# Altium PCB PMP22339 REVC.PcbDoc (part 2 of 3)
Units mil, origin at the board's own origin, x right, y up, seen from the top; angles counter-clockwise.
Board outline 4555 x 3750 mil, 4 copper layers (Top Layer, Signal Layer 2, Signal Layer 3, Bottom Layer), stack 62.6 mil thick; 180 components, 83 nets, 384 pads, 132 vias.
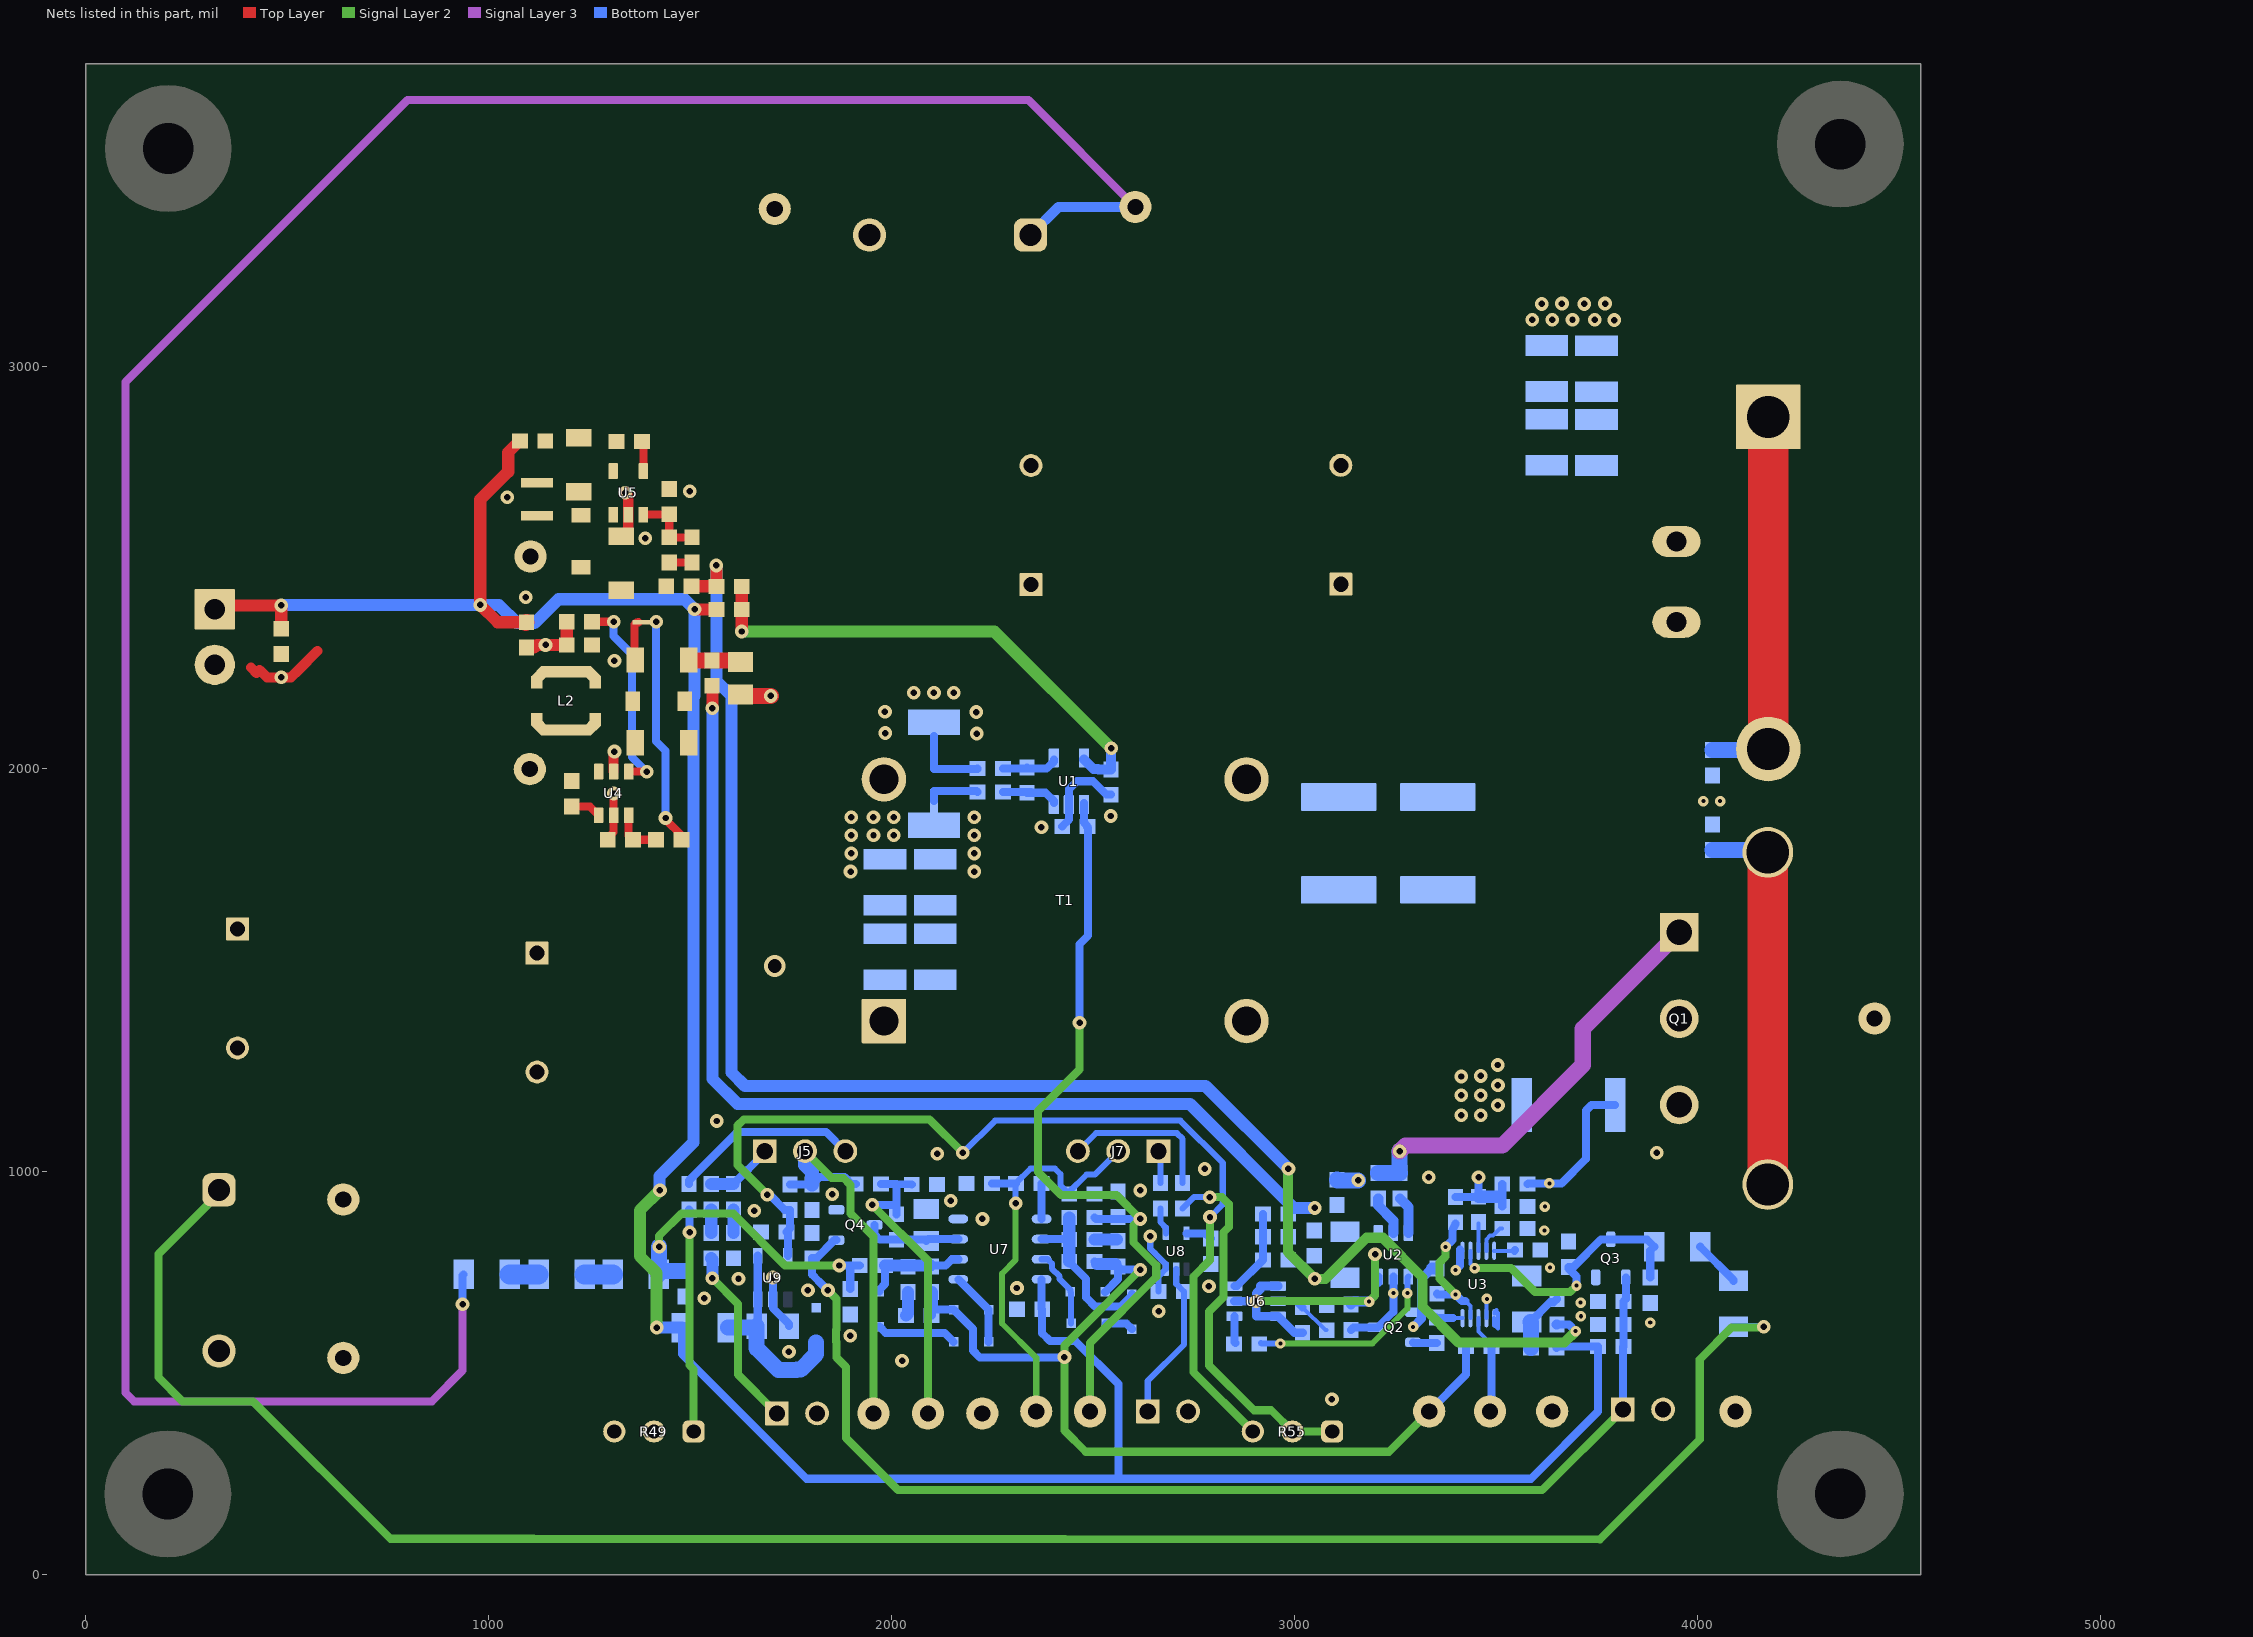
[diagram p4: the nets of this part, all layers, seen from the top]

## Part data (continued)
L2: library part CMP-0061351-2, "Inductor, Shielded Drum Core, Ferrite, 33 uH, 0.68 A, 0.42 ohm, SMD", Manufacturer=Coilcraft, Value1="0.42 ohm", Value2=0.68A, ValueDisplayed=33uH
LOGO2 LOGO3: library part CMP-0074835-1, "IEC 61010-1 High Voltage Warning"
Logo2: library part CMP-0074847-1, "FCC_disclaimer"
Logo3: library part CMP-0074769-1
NT1 NT2: library part CMP-0078142-2, "Single point connection between nets.", Manufacturer=N/A
Q1: library part CMP-0090000-1, "N-Channel 1.2kV 19A (Tc) 94W (Tc) Through Hole PG-TO247-3-41", Digikey Part Number=IMW120R140M1HXKSA1-ND, Input Capacitace At Vds="454pF @ 800V", Manufacturer="Infineon Technologies", Mouser Part Number=726-IMW120R140M1HXKS, Operating Temperature Range="-55°C to +175°C", Power_W=94W, Pulse Drain Current=32A, Typ Forward Diode Voltage=4.1V
Q2: library part CMP-0000344-2, "Transistor, PNP, 60 V, 0.6 A, SOT-23", Manufacturer="ON Semiconductor", Supplier Part Number 1=MMBT2907ALT1GOSCT-ND, Value1="0.6 A"
Q3 Q4: library part CMP-0000775-2, "MOSFET, N-CH, 60 V, 0.36 A, SOT-23", Alternate Manufacturer=None, Manufacturer=Nexperia, Supplier Part Number 1=568-5818-1-ND, Value2="0.6 nC"
R1 R4 R6 R8 R63: library part CMP-0022003-4, "RES, 10.0, 1%, 0.1 W, AEC-Q200 Grade 0, 0603", Manufacturer=Vishay-Dale, Power_W=100mW, Supplier Part Number 1=541-10.0HCT-ND, TempCo="100 ppm/C", Tolerance_%=1%, Value2=0.1W, Value_Code=10R0, ValueDisplayed=10.0
R2: library part CMP-0022447-4, "RES, 49.9 k, 1%, 0.1 W, AEC-Q200 Grade 0, 0603", Manufacturer=Vishay-Dale, Power_W=100mW, Supplier Part Number 1=541-49.9KHCT-ND, TempCo="100 ppm/C", Tolerance_%=1%, Value2=0.1W, Value_Code=49k9, ValueDisplayed=49.9k
R3: library part CMP-0015791-2, "RES, 0.05, 1%, 2 W, 2512", Manufacturer="Stackpole Electronics Inc", Power_W=2W, Supplier Part Number 1=CSRN2512FT50L0-ND, TempCo="200 ppm/C", Tolerance_%=1%, Value_Code=R050, ValueDisplayed=0.05
R7 R10 R11 R13: library part CMP-0017016-3, "RES, 499 k, 1%, 0.25 W, AEC-Q200 Grade 0, 1206", Manufacturer=Vishay-Dale, Power_W=250mW, Supplier Part Number 1=541-499KFCT-ND, TempCo="100 ppm/C", Tolerance_%=1%, Value2=0.25W, Value_Code=499k
R9 R19 R21 R26 R27 R28 R29 R30 R39 R50 R53 R62 R64 R101 R102: library part CMP-0025697-4, "RES, 0, 5%, 0.1 W, AEC-Q200 Grade 0, 0603", Manufacturer=Vishay-Dale, Power_W=100mW, Supplier Part Number 1=541-0.0GCT-ND, TempCo="200 ppm/C", Tolerance_%=5%, Value2=0.1W, Value_Code=0000, ValueDisplayed=0
R12: library part CMP-0022543-5, "RES, 649, 1%, 0.1 W, AEC-Q200 Grade 0, 0603", Manufacturer=Vishay-Dale, Power_W=100mW, Supplier Part Number 1=541-649HCT-ND, TempCo="100 ppm/C", Tolerance_%=1%, Value2=0.1W, Value_Code=649R, ValueDisplayed=649
R14 R24 R41 R46 R47 R54 R58 R59: library part CMP-0021998-4, "RES, 10.0 k, 1%, 0.1 W, AEC-Q200 Grade 0, 0603", Manufacturer=Vishay-Dale, Power_W=100mW, Supplier Part Number 1=541-10.0KHCT-ND, TempCo="100 ppm/C", Tolerance_%=1%, Value2=0.1W, Value_Code=10k0, ValueDisplayed=10.0k
R15: library part CMP-0022409-5, "RES, 402, 1%, 0.1 W, AEC-Q200 Grade 0, 0603", Manufacturer=Vishay-Dale, Power_W=100mW, Supplier Part Number 1=541-402HCT-ND, TempCo="100 ppm/C", Tolerance_%=1%, Value2=0.1W, Value_Code=402R, ValueDisplayed=402
R16: library part CMP-0017074-3, "RES, 590 k, 1%, 0.25 W, AEC-Q200 Grade 0, 1206", Manufacturer=Vishay-Dale, Power_W=250mW, Supplier Part Number 1=541-590KFCT-ND, TempCo="100 ppm/C", Tolerance_%=1%, Value2=0.25W, Value_Code=590k
R17: library part CMP-0022548-4, "RES, 66.5 k, 1%, 0.1 W, AEC-Q200 Grade 0, 0603", Manufacturer=Vishay-Dale, Power_W=100mW, Supplier Part Number 1=541-66.5KHCT-ND, TempCo="100 ppm/C", Tolerance_%=1%, Value2=0.1W, Value_Code=66k5, ValueDisplayed=66.5k
R18: library part CMP-0022077-4, "RES, 169 k, 1%, 0.1 W, AEC-Q200 Grade 0, 0603", Manufacturer=Vishay-Dale, Power_W=100mW, Supplier Part Number 1=541-169KHCT-ND, TempCo="100 ppm/C", Tolerance_%=1%, Value2=0.1W, Value_Code=169k
R20: library part CMP-0022380-4, "RES, 3.74 k, 1%, 0.1 W, AEC-Q200 Grade 0, 0603", Manufacturer=Vishay-Dale, Power_W=100mW, Supplier Part Number 1=541-3.74KHCT-ND, TempCo="100 ppm/C", Tolerance_%=1%, Value2=0.1W, Value_Code=3k74, ValueDisplayed=3.74k
R22: library part CMP-0022109-5, "RES, 1.00 k, 1%, 0.1 W, AEC-Q200 Grade 0, 0603", Manufacturer=Vishay-Dale, PartNumber=CRCW06031K00FKEA, Power_W=100mW, Supplier Part Number 1=541-1.00KHCT-ND, TempCo="100 ppm/C", Tolerance_%=1%, Value2=0.1W, Value_Code=1k00, ValueDisplayed=1.00k
R23 R51: library part CMP-0022204-4, "RES, 20.0 k, 1%, 0.1 W, AEC-Q200 Grade 0, 0603", Manufacturer=Vishay-Dale, Power_W=100mW, Supplier Part Number 1=541-20.0KHCT-ND, TempCo="100 ppm/C", Tolerance_%=1%, Value2=0.1W, Value_Code=20k0, ValueDisplayed=20.0k
R25: library part CMP-0077663-1, "RES, 0.033, 1%, 2 W, AEC-Q200 Grade 0, 2512", Manufacturer=Vishay-Dale, Power_W=2W, TempCo="75 ppm/C", Tolerance_%=1%, Value_Code=R033, ValueDisplayed=0.033
R31 R32: library part CMP-0021990-4, "RES, 100 k, 1%, 0.1 W, AEC-Q200 Grade 0, 0603", Manufacturer=Vishay-Dale, Power_W=100mW, Supplier Part Number 1=541-100KHCT-ND, TempCo="100 ppm/C", Tolerance_%=1%, Value2=0.1W, Value_Code=100k
R33: library part CMP-0022486-4, "RES, 52.3 k, 1%, 0.1 W, AEC-Q200 Grade 0, 0603", Manufacturer=Vishay-Dale, Power_W=100mW, Supplier Part Number 1=541-52.3KHCT-ND, TempCo="100 ppm/C", Tolerance_%=1%, Value2=0.1W, Value_Code=52k3, ValueDisplayed=52.3k
R34: library part CMP-0022093-4, "RES, 182 k, 1%, 0.1 W, AEC-Q200 Grade 0, 0603", Manufacturer=Vishay-Dale, Power_W=100mW, Supplier Part Number 1=541-182KHCT-ND, TempCo="100 ppm/C", Tolerance_%=1%, Value2=0.1W, Value_Code=182k
R35: library part CMP-0022043-4, "RES, 13.3 k, 1%, 0.1 W, AEC-Q200 Grade 0, 0603", Manufacturer=Vishay-Dale, Power_W=100mW, Supplier Part Number 1=541-13.3KHCT-ND, TempCo="100 ppm/C", Tolerance_%=1%, Value2=0.1W, Value_Code=13k3, ValueDisplayed=13.3k
R36 R38: library part CMP-0022109-5, "RES, 1.00 k, 1%, 0.1 W, AEC-Q200 Grade 0, 0603", Manufacturer=Vishay-Dale, Power_W=100mW, Supplier Part Number 1=541-1.00KHCT-ND, TempCo="100 ppm/C", Tolerance_%=1%, Value2=0.1W, Value_Code=1k00, ValueDisplayed=1.00k
R37: library part CMP-0022512-4, "RES, 5.49 k, 1%, 0.1 W, AEC-Q200 Grade 0, 0603", Manufacturer=Vishay-Dale, Power_W=100mW, Supplier Part Number 1=541-5.49KHCT-ND, TempCo="100 ppm/C", Tolerance_%=1%, Value2=0.1W, Value_Code=5k49, ValueDisplayed=5.49k
R40: library part CMP-0022252-4, "RES, 274 k, 1%, 0.1 W, AEC-Q200 Grade 0, 0603", Manufacturer=Vishay-Dale, Power_W=100mW, Supplier Part Number 1=541-274KHCT-ND, TempCo="100 ppm/C", Tolerance_%=1%, Value2=0.1W, Value_Code=274k
R42: library part CMP-0022213-4, "RES, 21.5 k, 1%, 0.1 W, AEC-Q200 Grade 0, 0603", Manufacturer=Vishay-Dale, Power_W=100mW, Supplier Part Number 1=541-21.5KHCT-ND, TempCo="100 ppm/C", Tolerance_%=1%, Value2=0.1W, Value_Code=21k5, ValueDisplayed=21.5k
R43: library part CMP-0022080-4, "RES, 16.5 k, 1%, 0.1 W, AEC-Q200 Grade 0, 0603", Manufacturer=Vishay-Dale, Power_W=100mW, Supplier Part Number 1=541-16.5KHCT-ND, TempCo="100 ppm/C", Tolerance_%=1%, Value2=0.1W, Value_Code=16k5, ValueDisplayed=16.5k
R44: library part CMP-0022482-4, "RES, 51.1 k, 1%, 0.1 W, AEC-Q200 Grade 0, 0603", Manufacturer=Vishay-Dale, Power_W=100mW, Supplier Part Number 1=541-51.1KHCT-ND, TempCo="100 ppm/C", Tolerance_%=1%, Value2=0.1W, Value_Code=51k1, ValueDisplayed=51.1k
R45: library part CMP-0022076-5, "RES, 165, 1%, 0.1 W, AEC-Q200 Grade 0, 0603", Manufacturer=Vishay-Dale, Power_W=100mW, Supplier Part Number 1=541-165HCT-ND, TempCo="100 ppm/C", Tolerance_%=1%, Value2=0.1W, Value_Code=165R, ValueDisplayed=165
R48: library part CMP-0022589-4, "RES, 75.0 k, 1%, 0.1 W, AEC-Q200 Grade 0, 0603", Manufacturer=Vishay-Dale, Power_W=100mW, Supplier Part Number 1=541-75.0KHCT-ND, TempCo="100 ppm/C", Tolerance_%=1%, Value2=0.1W, Value_Code=75k0, ValueDisplayed=75.0k
R49 R55: library part CMP-0065390-2, "Potentiometer, 100k Ohm, 0.5W, TH", Manufacturer=Bourns, Supplier Part Number 1=490-2876-ND
R52: library part CMP-0022116-4, "RES, 1.18 k, 1%, 0.1 W, AEC-Q200 Grade 0, 0603", Manufacturer=Vishay-Dale, Power_W=100mW, Supplier Part Number 1=541-1.18KHCT-ND, TempCo="100 ppm/C", Tolerance_%=1%, Value2=0.1W, Value_Code=1k18, ValueDisplayed=1.18k
R56: library part CMP-0022136-4, "RES, 1.91 k, 1%, 0.1 W, AEC-Q200 Grade 0, 0603", Manufacturer=Vishay-Dale, Power_W=100mW, Supplier Part Number 1=541-1.91KHCT-ND, TempCo="100 ppm/C", Tolerance_%=1%, Value2=0.1W, Value_Code=1k91, ValueDisplayed=1.91k
R57: library part CMP-0022268-4, "RES, 2.00 k, 1%, 0.1 W, AEC-Q200 Grade 0, 0603", Manufacturer=Vishay-Dale, Power_W=100mW, Supplier Part Number 1=541-2.00KHCT-ND, TempCo="100 ppm/C", Tolerance_%=1%, Value2=0.1W, Value_Code=2k00, ValueDisplayed=2.00k
R60: library part CMP-0022449-4, "RES, 4.02 k, 1%, 0.1 W, AEC-Q200 Grade 0, 0603", Manufacturer=Vishay-Dale, Power_W=100mW, Supplier Part Number 1=541-4.02KHCT-ND, TempCo="100 ppm/C", Tolerance_%=1%, Value2=0.1W, Value_Code=4k02, ValueDisplayed=4.02k
R61: library part CMP-0016687-2, "RES, 1.00 k, 1%, 0.25 W, 1206", Manufacturer=Vishay-Dale, Power_W=250mW, Supplier Part Number 1=541-1.00KFCT-ND, TempCo="100 ppm/C", Tolerance_%=1%, Value2=0.25W, Value_Code=1k00, ValueDisplayed=1.00k
R100: library part CMP-0021282-3, "RES, 499, 1%, 0.125 W, AEC-Q200 Grade 0, 0805", Manufacturer=Vishay-Dale, Power_W=125mW, Supplier Part Number 1=541-499CCT-ND, TempCo="100 ppm/C", Tolerance_%=1%, Value2=0.125W, Value_Code=499R, ValueDisplayed=499
T1: library part CMP-0092085-1, "COUPLED INDUCTOR 160uH", Manufacturer="Renco Electronics", Operating Temperature Range=to, Test Frequency=100kHz, Tolerance_%=15%
TP1 TP2 TP4 TP7 TP9 TP10 TP11 TP16 TP17: library part CMP-0055137-1, "Test Point, Miniature, Red, TH", Color=Red, Manufacturer=Keystone, Supplier Part Number 1=36-5000-ND
TP3 TP5 TP8 TP12 TP15: library part CMP-0055138-1, "Test Point, Miniature, Black, TH", Color=Black, Manufacturer=Keystone, Supplier Part Number 1=36-5001-ND
TP13 TP14: library part CMP-0055140-1, "Test Point, Miniature, Orange, TH", Color=Orange, Manufacturer=Keystone, Supplier Part Number 1=36-5003-ND
U1: library part CMP-0750213-2, "INA293 High-Voltage, High Bandwidth, Unidirectional, 110-V Common-Mode, Current-Sense Amplifier, DBV0005A (SOT-23-5)", Alternate Manufacturer="Texas Instruments", Alternate PartNumber=INA293A1IDBVT
U2: library part CMP-0066954-1, "2.5-A, 5-A, 35-VMAX VDD FET and IGBT Single Gate Driver, DBV0006A (SOT-23-6)", Alternate Manufacturer="Texas Instruments"
U3: library part CMP-0076391-1, "2.2MHz 60-V Low Side Controller for Boost, SEPIC and Flyback, DGS0010A (VSSOP-10)", Alternate Manufacturer="Texas Instruments", Alternate PartNumber=LM5022QDGSTQ1
U4: library part CMP-0076376-2, "SIMPLE SWITCHER 4.5V to 42V, 0.3A Step-Down DC/DC Switching Regulator in SOT-23, DDC0006A (SOT-23-T-6)", Alternate Manufacturer="Texas Instruments", Alternate PartNumber=LMR14203XMKE/NOPB
U5: library part CMP-0066120-1, "SIMPLE SWITCHER(R) 2.7V to 14V, 1A Step-Up Regulator in SOT-23 Package, DBV0005A (SOT-23-5)", Alternate Manufacturer="Texas Instruments"
U6: library part CMP-0074248-2, "36-V Voltage Detector, DDC0006A (SOT-23-T-6)", Alternate Manufacturer="Texas Instruments", Alternate PartNumber=TPS3711DDCT
U7: library part CMP-0043594-1, "LinCMOS(TM) Precision Dual Operational Amplifier, 4 to 16 V, -40 to 85 degC, 8-pin SOIC (D8), Green (RoHS & no Sb/Br)", Manufacturer="Texas Instruments", Rating=Catalog, Total Supply Voltage(Max)(+5V is 5, +/-5V is 10)=16, Total Supply Voltage(Min)(+5V is 5, +/-5V is 10)=4
U8: library part CMP-0051720-2, "Single Buffer Gate, DCK0005A, LARGE T&R", F @ Nom Voltage(Max)(Mhz)=150, Generic Part Number=SN74LVC1G34, ICC @ Nom Voltage(Max)(mA)=0.001, Manufacturer="Texas Instruments", Operating Temperature Range(C)="-40 to 125,-40 to 85", Rating=Catalog, tpd @ Nom Voltage(Max)(ns)=8.6,4.4,4.1,3.2, Voltage(Nom)(V)=1.8,2.5,3.3,5
U9: library part CMP-0081352-1, "0.05% 20ppm/degC Drift Precision Series Voltage Reference with Shutdown Enable, DBV0005A (SOT-23-5)", Alternate Manufacturer="Texas Instruments", Alternate PartNumber=LM4132AMFX-3.0/NOPB, Operating Temprature Range="-40 to 125 C", Rating=Catalog

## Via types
v1: diameter 34, hole 16, Top Layer to Bottom Layer, 110 vias
v2: diameter 26, hole 10, Top Layer to Bottom Layer, 21 vias
v3: diameter 54, hole 34, Top Layer to Bottom Layer, 1 vias

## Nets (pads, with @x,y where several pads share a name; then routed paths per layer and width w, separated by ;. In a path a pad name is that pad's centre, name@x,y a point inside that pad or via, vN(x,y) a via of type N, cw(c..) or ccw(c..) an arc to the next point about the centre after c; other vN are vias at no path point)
3VREF: C43.1 C45.2 R42.2 R55.3 U8.5 U9.5 | length 2589.8
  Signal Layer 2 w20: v1(1691,943.25) 1617.73,1016.51 1617.73,1114.73 1633,1130 2094,1130 v1(2177,1047) ; v1(2790.38,887.5) 2790.38,781.01 2748.86,739.49 2748.86,503.01 R55.3@2896.69,355.18
  Bottom Layer w15: v1(2177,1047) 2257,1127 2717,1127 2822,1022 2822,950.62 2822.37,950.25 2822.37,923.43 2822,923.06 2822,919.13 v1(2790.38,887.5)
  Bottom Layer w20: v1(1691,943.25) 1696.75,943.25 1734.66,905.34 R42.2@1747.4,905.34 1747.4,858.74 C43.1@1738.9,850.24 1742.55,846.59 U9.5@1742.55,791.5 ; U8.5@2732.13,847.1 2779.4,847.1 C45.2@2790.38,836.12 ; v1(2790.38,887.5) C45.2@2790.38,836.12 ; C45.2@2792.19,834.3 C45.2@2790.38,836.12
+12V: C25.2 C34.2 J4.1 R14.2 R26.1 R29.1 R61.2 R62.2 R63.1 U7.8 | length 7278.1
  Top Layer w30: J4.1@320,2396.39 329.27,2405.66 v1(485,2405.66) C25.2@485,2347.99 ; R26.1@1077.3,2814.38 1048.52,2785.61 1048.52,2737.52 1047.91,2737.52 979,2668.61 v1(979,2407) 1022.02,2363.98 R29.1@1093.79,2363.98 ; v1(1511,2396) R62.2@1565.06,2396
  Top Layer w40: R29.1@1091.81,2362 R29.1@1093.79,2363.98
  Signal Layer 2 w30: v1(1416.94,613.15) 1416.94,748.66 1375,790.6 1375,904.29 v1(1425,954.29)
  Bottom Layer w20: R61.2@1479.86,613.15 1479.86,547.14 1789,238 2563,238 ; U7.8@2372.26,732.82 2372.26,660.26 C34.2@2373.85,658.68 2373.85,599.06 2392.9,580 2456,580 2563,473 2563,238 ; R63.1@3650.5,563 3653.54,566.04 R14.2@3753.62,566.04 3753.62,404.62 3587,238 2563,238
  Bottom Layer w30: v1(485,2405.66) 486.34,2407 v1(979,2407) 1025.08,2407 1070.08,2362 1114,2362 1173,2421 1486,2421 v1(1511,2396) 1511,2181 1508,2178 1508,1072.8 1424,988.8 1424,955.29 v1(1425,954.29) ; v1(1416.94,613.15) R61.2@1479.86,613.15
+18V: C16.1 C17.1 R6.1 R27.2 R28.2 R33.2 R64.2 U2.3 | length 4091.1
  Top Layer w30: R28.2@1503.64,2453.38 1564.68,2453.38 R64.2@1565.06,2453 v1(1565.06,2505)
  Signal Layer 2 w25: v1@2984,1007 2984,800.27 v1(3050.12,734.15) 3076.99,734.15 3179.01,836.17 3219.28,836.17 3318,737.45 3318,665.33 3407.69,575.65 3532,576.25 3670.02,576.25 v2(3698,604.23)
  Bottom Layer w20: U2.3@3208,724 U2.3@3207.99,739.51 ; R6.1@3651.5,621 3681.23,621 v2(3698,604.23)
  Bottom Layer w25: R6.1@3651,620.5 R6.1@3651.5,621
  Bottom Layer w30: v1(1565.06,2505) 1565.06,2218.94 1603,2181 1603,1246 1636,1213 2779.29,1213 v1(2985.12,1007.18)
-5V: C16.2 C17.2 C27.1 C31.1 R15.1 R19.2 R38.1 R39.1 U2.4 U6.2 U6.4 U6.6 | length 3364.7
  Top Layer w30: R39.1@1553.96,2206.34 1555.12,2205.19 v1(1555.12,2150.18)
  Signal Layer 2 w20: v1(2905.12,678.68) 3183.82,678.68 v2(3185.12,677.38) 3200.12,692.38 v1(3200.12,795.18)
  Bottom Layer w22: U6.2@2850.98,678.68 v1(2905.12,678.68) ; U6.4@2959.25,716.08 2916.13,716.08 2916.13,709.38 2905.12,698.36 v1(2905.12,678.68) ; C27.1@3020,600.5 3000.02,600.5 U6.6@2959.25,641.28 2905.2,641.28 2905.2,678.6 v1(2905.12,678.68)
  Bottom Layer w25: R15.1@3140.12,670.18 3147.32,677.38 v2(3185.12,677.38)
  Bottom Layer w30: v1(1555.12,2150.18) 1555.12,1230.88 1618,1168 2740.7,1168 2998.53,910.18 v1(3050.12,910.18)
COMP: R50.2 TP14.1 U3.3 | length 246.2
  Bottom Layer w10: U3.3@3456.5,636.51 3456.5,603.5 3488.78,571.22 R50.2@3488.78,566.04
  Bottom Layer w20: TP14.1@3485.12,405.18 3488.78,408.84 R50.2@3488.78,566.04
DIS: C20.1 J3.1 Q3.1 Q4.1 R14.1 R23.2 R51.2 | length 2956.2
  Signal Layer 2 w20: v1(1842,705.46) 1863,684.46 1863,607.72 1862.54,607.26 1862.54,578.37 1863,577.92 1863,539 1887,515 1887,339 2016,210 3614.94,210 J3.1@3815.12,410.18
  Bottom Layer w20: v1(1842,705.46) 1827.27,720.18 1827.27,720.28 1806.85,740.71 1806.74,740.71 1802.4,745.05 R51.2@1802.4,785.35 1813.35,785.35 1858.42,830.42 Q4.1@1862.91,830.42 ; J3.1@3815.12,410.18 3815.12,564.54 R14.1@3816.61,566.04 R23.2@3816.61,678.36 3822.52,684.27 Q3.1@3822.52,737.8
EN-drv: R30.1 U2.1 | length 480.2
  Signal Layer 2 w15: v2(2965.12,573.68) 3193.58,573.68 3280.39,660.49 v2(3280.39,698.65)
  Bottom Layer w15: R30.1@2916.61,574.71 2917.64,573.68 v2(2965.12,573.68) ; v2(3280.39,698.65) 3280.39,737.11 U2.1@3282.79,739.51
GND: C1.1 C2.1 C6.2 C7.2 C12.1 C13.2 C14.2 C15.2 C18.2 C19.2 C20.2 C21.2 C22.2 C24.1 C25.1 C26.2 C28.1 C34.1 C35.2 C36.2 C37.2 C38.2 C41.2 C42.2 C43.2 C44.2 C45.1 C100.1 C101.1 C102.1 D10.2 J1.2 J2.2 J3.2 J4.2 J6.2 J8.2 L2.2 NT1.1 NT2.2 Q2.1 Q3.2 Q4.2 R2.1 R3.1 R18.1 R19.1 R20.1 R23.1 R24.1 R25.1 R35.1 R49.2 R49.3 R51.1 R52.1 R59.1 R60.1 R100.2 R101.1 R102.1 TP3.1 TP5.1 TP8.1 TP12.1 TP15.1 U1.2 U3.2 U3.6 U5.2 U7.4 U8.3 U9.2 | length 1379.3
  Top Layer w20: C28.1@1363.19,2270.18 1361.42,2271.95 1361.42,2358.41 1366.79,2363.78 1371.75,2363.78 NT2.2@1371.95,2363.98
  Top Layer w25: 410,2251.5 424,2237.5 431.5,2245 449.35,2227.15 v1(485,2227.15) 509.14,2227.15 526.99,2245 575,2293.01 ; C26.2@1328.79,2577.38 1346.39,2594.97 U5.2@1346.39,2630.9 1346.39,2677.64 v1(1339,2685.03)
  Top Layer w40: R100.2@1625,2185 1629,2181 v1(1700,2181)
  Bottom Layer w10: 3409.24,805.41 3411.11,803.53 3412.09,802.56 3412.09,807.28 3415.53,803.83 U3.6@3417.13,803.83 ; U3.2@3476.18,636.51 3476.18,682.69 v2(3477.67,684.17)
  Bottom Layer w15: v1(2642,840) 2642,809.2 2653.38,797.82 2653.48,797.82 2680.94,770.36 U8.3@2680.94,758.51 2662.92,740.49 R59.1@2662.92,702.52
  Bottom Layer w20: v1(1705.14,737.36) U9.2@1705.14,683.23 1705.14,661.86 1745.14,621.86 C44.2@1745.14,616.64 ; R2.1@2423.62,1857.39 2440.12,1873.89 2440.12,1949.56 2459.8,1969.25 2499.75,1969.25 2533.1,1935.9 C1.1@2545.12,1935.9 ; v2(3400.12,755.6) 3411.11,766.6 3411.11,803.53 3411.11,807.28
  Bottom Layer w22: v2(3294.42,614.7) 3315.58,635.86 3315.58,734.76 C18.2@3340.98,760.15
  Bottom Layer w30: C18.2@3340.98,760.15 C18.2@3353.41,760.15
  Bottom Layer w40: R19.1@3105.7,980.14 3107.2,978.65 v1(3158.04,978.65)
  other v1: 3093,435 2026,531 1745.14,552.82 1897.42,592.82 2662.92,653.65 1535,686 1792.4,705.84 2311.22,711.36 2787.76,715.51 1620,734.15 2225.44,882.82 1659.2,903.37 2146.87,927.82 1852.4,944.27 2617.4,953.57 3333,986.63 2777,1007 2113,1045 3899,1047 1566,1126 3413.72,1140 3462.19,1140 3505,1165 3413.72,1190 3462.19,1190 3505,1215 3413.72,1236.47 3462.19,1237.82 3504.94,1265 1898.19,1745.18 2205.12,1745.18 1900.12,1790.18 2205.12,1790.18 1900.12,1835.18 1955.12,1835.18 2005.12,1835.18 2205.12,1835.18 2372,1855.25 1900,1880 1955,1880 2005.12,1880.18 2205.12,1880.18 2543.7,1883 1311.97,2268.05 1092,2426 1388.79,2572.82 1046,2674 1499,2689 3794,3114 3590.12,3115.18 3640.12,3115.18 3690.12,3115.18 3745.12,3115.18 3614,3154 3719,3154 3664,3155 3770.99,3155
  other v2: 3883.19,625.45 3711,641.28 3710.23,675.16 3634.33,761.84 3620.5,854.17 3621.5,913.19 4015,1920 4056.7,1920
  other v3: 1710.19,1510.45
"MB CHG ISNS": C41.1 R2.2 R54.1 TP1.1 U1.1 | length 1968.5
  Signal Layer 2 w20: v1(2466.64,1370) 2466.32,1369.68 2466.32,1254.16 2363,1150.84 2363,999.38 2420.38,942 2558.22,942 v1(2617.4,882.82) 2615.67,882.82 2600,867.15 2600,825 2657,768 2657,739.21 2492.4,574.61 TP1.1@2492.4,405.18
  Bottom Layer w20: v1(2466.64,1370) 2466.64,1564.64 2488,1586 2488,1852.78 2485,1855.78 R2.2@2486.61,1857.39 2477.52,1866.49 U1.1@2477.52,1915.11 ; R54.1@2503.9,886.5 2507.58,882.82 v1(2617.4,882.82)
"MB CHG VSNS": C35.1 R16.1 R24.2 R41.1 | length 796.3
  Signal Layer 2 w20: v1(1423,813.88) 1423,841 1478.56,896.56 1576,896.56 1576.56,896 1607.04,896 1735.76,767.27 v1(1870.15,767.27)
  Bottom Layer w20: v1(1870.15,767.27) 1897.42,767.27 ; C35.1@1897.42,708.88 1897.42,767.27 ; R41.1@1920.9,766.82 1920.45,767.27 1897.42,767.27
  Bottom Layer w40: R16.1@1421.89,745.18 R16.1@1423,746.29 ; v1(1423,813.88) R16.1@1423,746.29 ; R24.2@1487,753.5 1430.21,753.5 R16.1@1423,746.29
NetC1_2: C1.2 R62.1 R64.1 U1.5 | length 1279
  Top Layer w30: v1(1628.05,2341) R62.1@1628.05,2396 R64.1@1628.05,2453
  Signal Layer 2 w30: v1(1628.05,2341) 2255,2341 v1(2545,2051)
  Bottom Layer w25: U1.5@2477.52,2023.38 2501.28,1999.62 2512.34,1999.62 2513.06,1998.89 C1.2@2545.12,1998.89 2545.12,2050.88 v1(2545,2051)
NetC3_2: C3.2 C6.1
NetC4_2: C4.2 C7.1
NetC5_1: C5.1 R4.2 U1.3 | length 152.1
  Bottom Layer w20: R4.2@2276.61,1942.39 2346.31,1942.39 C5.1@2348,1940.7 ; C5.1@2336.14,1940.7 C5.1@2348,1940.7 ; U1.3@2402.71,1915.11 2402.71,1920.03 2382.05,1940.7 C5.1@2348,1940.7
NetC5_2: C5.2 R1.2 U1.4 | length 142.6
  Bottom Layer w20: R1.2@2276.61,2000.72 C5.2@2333.17,2000.72 ; C5.2@2336.14,2003.69 C5.2@2333.17,2000.72 ; U1.4@2402.71,2023.38 2402.71,2018.43 2385,2000.72 C5.2@2333.17,2000.72
NetC8_1: C8.1 C11.1 Q1.2 T1.4 TP7.1
NetC8_2: C8.2 C11.2 D1.2 T1.3
NetC9_2: C9.2 C13.1
NetC10_2: C10.2 C14.1
NetC15_1: C15.1 R6.2 R63.2 U3.1 | length 266.9
  Bottom Layer w10: U3.1@3495.87,636.51 3495.87,620.07 3504.94,611 3504.94,649.72 3501.65,653 3496.8,648.15 3496.8,651.98 3501.67,656.86 ; C15.1@3576.31,636.51 3585.73,627.08 C15.1@3576.5,627.08
  Bottom Layer w20: C15.1@3585.73,627.08 3634.65,676 3643.51,676 R6.2@3651.5,684
  Bottom Layer w40: C15.1@3585.73,627.08 3587.5,625.31 R63.2@3587.5,563
NetC18_1: C18.1 R17.2 U3.4 | length 334.1
  Signal Layer 2 w20: v2(3375.12,813.33) 3375.12,789.8 3360,774.68 3360,735.29 v2(3400.12,695.18)
  Bottom Layer w10: 3424,679 3436.81,666.19 U3.4@3436.81,636.51
  Bottom Layer w20: C18.1@3353.41,697.16 3355.39,695.18 v2(3400.12,695.18) 3416.29,679 3424,679 ; v2(3375.12,813.33) 3375.12,813.98 3392,830.87 3392,855.86 R17.2@3400.12,871.57
NetC19_1: C19.1 U3.10 | length 52
  Bottom Layer w10: U3.10@3495.87,803.83 3517,803.83 C19.1@3545.67,803.83
  Bottom Layer w20: C19.1@3545.67,803.83 C19.1@3547.25,805.41
NetC21_1: C21.1 R17.1 R21.1 R22.1 | length 224.9
  Bottom Layer w20: R17.1@3400.12,937.5 3400.44,937.82 R21.1@3457.28,937.82 ; R21.1@3457,938.1 v1(3457,986.63) ; 3502.19,937.82 C21.1@3515.75,924.26 ; C21.1@3515.75,914.17 C21.1@3515.75,924.26 ; R22.1@3515.75,969.17 C21.1@3515.75,924.26
  Bottom Layer w30: R21.1@3457.28,937.82 3502.19,937.82
NetC22_1: C22.1 L1.1 R26.2 R31.2 U5.5
NetC23_1: C23.1 D3.1 L2.1 TP17.1 U4.6
NetC23_2: C23.2 U4.1 | length 75.6
  Top Layer w20: C23.2@1206.11,1906.55 1250.9,1906.55 U4.1@1272.67,1884.78
NetC24_2: C24.2 C30.1 R29.2 R32.1 U4.5 | length 210.9
  Top Layer w25: U4.5@1310.08,1993.05 1310.08,2041.16 v1(1311.97,2043.05)
  Top Layer w30: R29.2@1093.79,2300.99 1112.88,2300.99 1119.47,2307.58 v1(1141.12,2307.58) C24.2@1193.62,2307.58 R32.1@1193.62,2365.18
NetC26_1: C26.1 C29.2 D2.1 R28.1 R34.2 | length 67.3
  Top Layer w20: R28.1@1440.64,2453.38 R28.1@1448.14,2460.87 ; R34.2@1448.14,2511.88 C29.2@1504.79,2511.88
NetC27_2: C27.2 R27.1 U6.5 | length 150.7
  Bottom Layer w10: C27.2@3020,663.5 3076.87,606.63 R27.1@3080.12,606.63
  Bottom Layer w20: U6.5@2959.25,678.68 3004.82,678.68 C27.2@3020,663.5
NetC28_2: C28.2 C30.2 D3.2 R36.1 R39.2 R100.1 U4.2 | length 251
  Top Layer w20: R36.1@1295.47,1824.03 1295.47,1828.21 1310.08,1842.81 U4.2@1310.08,1884.78 v1(1310.08,1938.91)
  Top Layer w40: C28.2@1497.05,2270.18 1497.89,2269.33 R39.2@1553.96,2269.33 1620.67,2269.33 R100.1@1625,2265
NetC29_1: C29.1 R34.1 R35.2 U5.3 | length 178.4
  Top Layer w20: U5.3@1383.79,2630.9 1447.16,2630.9 R35.2@1448.14,2631.88 R34.1@1448.14,2574.87 C29.1@1504.79,2574.87
NetC31_2: C31.2 R33.1 R38.2 U6.3 | length 211.6
  Bottom Layer w20: U6.3@2850.98,716.08 2856.89,716.08 R33.1@2921.67,780.86 R38.2@2921.67,838.56 C31.2@2921.67,894.92
NetC32_1: C32.1 D4.1 R40.1 R41.2 U7.2 | length 261.5
  Bottom Layer w20: D4.1@1969.64,702.4 1969.64,707.22 1983.9,721.48 R41.2@1983.9,766.82 ; C32.1@2098.9,764.77 2096.85,766.82 2134,766.82 2150,782.82 U7.2@2165.57,782.82
  Bottom Layer w30: R41.2@1983.9,766.82 C32.1@2096.85,766.82
NetC32_2: C32.2 C33.1 C39.2 C40.1 D6.2 D9.2 R50.1 TP13.1 | length 2314.4
  Signal Layer 2 w20: v1(2617.4,756.86) 2429,568.46 v1(2429,540) 2429,358 2482,305 3234.28,305 TP13.1@3334.46,405.18
  Bottom Layer w20: C33.1@2098.9,642.82 2099.9,643.83 2099.9,661.52 2103.61,657.82 D6.2@2154.09,657.82 2202,609.91 2202,556 2219,539 2428,539 v1(2429,540) ; C32.2@2098.9,701.78 C32.2@2099.9,700.77 ; C39.2@2503.9,776.83 C39.2@2509.41,771.31 ; D9.2@2530.25,701.82 2562.4,733.97 C40.1@2562.4,765 ; C40.1@2556.09,771.31 C40.1@2562.4,765 ; v1(2617.4,756.86) 2570.54,756.86 C40.1@2562.4,765 ; TP13.1@3334.46,405.18 3425.79,496.51 R50.1@3425.79,566.04
  Bottom Layer w30: C33.1@2099.9,661.52 C32.2@2099.9,700.77 ; C39.2@2509.41,771.31 C40.1@2556.09,771.31
NetC33_2: C33.2 R40.2 | length 60.7
  Bottom Layer w30: C33.2@2035.9,642.82 2041.2,648.12 R40.2@2041.2,701.32
NetC36_1: C36.1 J5.2 R42.1 R46.1 TP10.1 | length 1008.4
  Signal Layer 2 w20: J5.2@1785.12,1050.91 1851.02,985 1880.06,985 1898.19,966.87 1898.19,896.56 1955.12,839.63 TP10.1@1955.12,400.18
  Bottom Layer w20: R42.1@1747.4,968.34 C36.1@1802.4,968.34 1820.7,986.63 1882.91,986.63 1900.43,969.11 R46.1@1911.06,969.11
  Bottom Layer w35: J5.2@1785.12,1050.91 1785.12,1016.88 1799,1003 1802.4,1003 C36.1@1802.4,968.34
NetC37_1: C37.1 R46.2 R47.1 TP11.1 | length 786.2
  Signal Layer 2 w20: v1(1952,917.8) 2090.12,779.68 TP11.1@2090.12,400.18
  Bottom Layer w20: v1(1952,917.8) 2012.46,917.8 ; R46.2@1974.05,969.11 2012.66,969.11 ; R47.1@2012.66,894.31 2012.46,894.51 2012.46,917.8 ; C37.1@2049.97,968.34 2012.66,969.11 ; 2012.46,917.8 2012.66,918 2012.66,969.11
NetC38_1: C38.1 Q4.3 R47.2 U7.3 | length 240.4
  Bottom Layer w20: Q4.3@1957.4,867.82 1957.4,844.6 1970.68,831.32 R47.2@2012.66,831.32 2082.6,831.32 C38.1@2086.1,827.82 2091.1,832.82 U7.3@2165.57,832.82
NetC39_1: C39.1 D7.1 R53.1 R54.2 U7.6 | length 422.6
  Bottom Layer w20: U7.6@2372.26,832.82 2439.58,832.82 R53.1@2440.9,831.5 ; C39.1@2440.9,776.83 2440.9,776.15 2483,734.06 2483,688 2505.3,665.7 2569.72,665.7 2596.48,692.46 D7.1@2596.48,696.12
  Bottom Layer w30: C39.1@2440.9,776.83 R53.1@2440.9,831.5 R54.2@2440.9,886.5
NetC40_2: C40.2 R53.2 | length 60
  Bottom Layer w20: C40.2@2558.9,831.5 C40.2@2562.4,827.99
  Bottom Layer w30: R53.2@2503.9,831.5 C40.2@2558.9,831.5
NetC42_1: C42.1 J7.2 R58.1 R60.2 TP16.1 | length 1035.5
  Signal Layer 2 w15: v1(2308,922) 2308,781.25 2274,747.25 2274,623.34 2359.05,538.28 TP16.1@2359.05,405.18
  Bottom Layer w15: v1(2308,922) 2308,970.59 R58.1@2308.7,971.29 ; R58.1@2309.15,970.84 R58.1@2308.7,971.29 ; J7.2@2562.4,1050.91 2504.49,993 2483.82,993 2440.9,950.09 R60.2@2440.9,944.27 2419,966.18 2419,994.31 2405.31,1008 2345.41,1008 R58.1@2308.7,971.29
  Bottom Layer w20: C42.1@2248.9,971.29 R58.1@2308.7,971.29
NetC44_1: C44.1 D10.1 R61.1 U9.3 U9.4 | length 517.8
  Bottom Layer w20: C44.1@1665.14,616.64 1667.74,619.24 U9.3@1667.74,683.23 U9.4@1667.74,791.5
  Bottom Layer w40: R61.1@1594.03,613.15 1661.65,613.15 C44.1@1665.14,616.64 1665.14,561.86 1719.06,507.94 1763.73,507.94 1764.79,509 1774.12,509 1812.4,547.28 D10.1@1812.4,575.97
NetC102_2: C102.2 Q3.3 R10.1 R20.2 U3.7 | length 716.2
  Signal Layer 2 w20: v2(3447,760.73) 3537.68,760.73 3597.28,701.13 3684.09,701.13 v2(3700.12,717.16)
  Bottom Layer w10: U3.7@3436.81,803.83 3436.81,771.31 3447,761.12 v2(3447,760.73)
  Bottom Layer w20: v2(3700.12,717.16) 3700.12,739.74 3680.12,759.74 R20.2@3680.12,763.68 3692.34,763.68 3760.95,832.29 Q3.3@3785.12,832.29 3874.62,832.29 R10.1@3893.03,813.88 3883.19,804.03 C102.2@3883.19,737.33
NetD2_2: D2.2 L1.2 TP9.1 U5.1
NetD4_2: D4.2 D5.2 | length 200.2
  Bottom Layer w20: D4.2@1969.64,615.79 1985.42,600 2131.91,600 D5.2@2154.09,577.82
NetD5_1: D5.1 D6.1 U7.1 | length 186.2
  Bottom Layer w20: U7.1@2165.57,732.82 2165.71,732.82 D6.1@2240.71,657.82 D5.1@2240.71,577.82
NetD7_2: D7.2 D8.2 | length 69.8
  Bottom Layer w20: D8.2@2532.43,623.44 2582.56,623.44 D7.2@2596.48,609.51
NetD8_1: D8.1 D9.1 U7.7 | length 198.7
  Bottom Layer w15: U7.7@2372.26,782.82 2387.43,782.82 2398,772.25 2398,759.6 2417.11,740.49 2417.11,733.49 2443.64,706.97 D9.1@2443.64,701.82 2445.81,699.65 D8.1@2445.81,623.44
NetH1_1: H1.1 H1.2 R102.2 | length 963.6
  Top Layer w100: H1.2@4176.12,2049.18 H1.1@4176.12,2873.59
  Bottom Layer w40: R102.2@4038,2046.5 4173.44,2046.5 H1.2@4176.12,2049.18
NetH2_1: H2.1 H2.2 R101.2 | length 964.1
  Top Layer w100: H2.2@4175.12,967.97 H2.1@4175.12,1792.38
  Bottom Layer w40: R101.2@4038,1798.5 4168.99,1798.5 H2.1@4175.12,1792.38
NetJ5_1: J5.1 R45.2 R48.2 | length 168.8
  Bottom Layer w20: R48.2@1607.4,969.31 1685.12,1047.03 J5.1@1685.12,1050.91
  Bottom Layer w30: R45.2@1552.4,969.31 R48.2@1607.4,969.31
NetJ5_3: J5.3 R43.2 | length 465.9
  Bottom Layer w20: R43.2@1497.4,969.31 1497.4,977.98 1617.73,1098.31 1837.71,1098.31 J5.3@1885.12,1050.91
NetJ6_1: J6.1 R44.1 | length 452.6
  Signal Layer 2 w20: v1(1555.12,735.47) 1619,671.59 1619,496.29 J6.1@1715.12,400.18
  Bottom Layer w30: R44.1@1552.4,785.35 1555.12,782.63 v1(1555.12,735.47)
NetJ7_1: J7.1 R57.2 | length 80.9
  Bottom Layer w15: J7.1@2662.4,1050.91 2667.4,1045.91 R57.2@2667.4,972.06
NetJ7_3: J7.3 R56.2 | length 394
  Bottom Layer w15: J7.3@2462.4,1050.91 2507.3,1095.81 2708.19,1095.81 2722.4,1081.6 R56.2@2722.4,972.06
NetJ8_1: J8.1 R59.2 U8.2 | length 398.7
  Bottom Layer w15: J8.1@2635.89,405.18 2635.89,480.89 2725.91,570.91 R59.2@2725.91,702.52 2706.53,721.9 U8.2@2706.53,758.51
NetNT1_2: NT1.2 R4.1 | length 135.1
  Bottom Layer w20: NT1.2@2105.12,1920.18 2105.12,1945.49 2210.52,1945.49 R4.1@2213.62,1942.39
NetNT2_1: NT2.1 R37.2 | length 567.6
  Top Layer w20: v1(1439,1878) 1439,1874.58 1478.46,1835.11 R37.2@1478.46,1824.03 R37.2@1478.7,1824.27
  Bottom Layer w20: v1(1415.47,2365.18) 1415.47,2068.53 1439,2045 v1(1439,1878)
NetQ1_1: Q1.1 R8.2 R9.2 | length 1080.8
  Signal Layer 3 w40: v1(3261.18,1050.91) 3275.27,1065 3515.65,1065 3715.65,1265 3715.65,1354.88 Q1.1@3955.12,1594.35
  Bottom Layer w40: R9.2@3207.99,996.47 R8.2@3262.2,996.47 3261.18,997.5 v1(3261.18,1050.91)
NetQ1_3: Q1.3 R22.2 R25.2 | length 369.2
  Bottom Layer w20: R22.2@3578.74,969.17 3580.41,970.84 v2(3632.8,970.84) 3662.84,970.84 3724.09,1032.09 3724.09,1152.21 3737.65,1165.77 R25.2@3796.14,1165.77
NetQ2_2: Q2.2 R12.2 | length 59.2
  Bottom Layer w20: Q2.2@3294.42,576.25 3295.54,575.13 R12.2@3353.16,575.13
NetQ2_3: Q2.3 R15.2 U2.2 | length 211.1
  Bottom Layer w20: R15.2@3140.12,607.18 3146.58,613.65 Q2.3@3199.94,613.65 3206.65,613.65 3245.39,652.39 v2(3245.39,698.65) U2.2@3245.39,739.51
NetR1_1: R1.1 R3.2 T1.2 | length 189.9
  Bottom Layer w20: 2105.12,2081.32 2105.12,2000.18 2213.08,2000.18 R1.1@2213.62,2000.72
  other v1: 2211.12,2087.73 1983.9,2088.84 2210,2141.04 1983.42,2142 2055,2189 2105.12,2189 2154.09,2189
NetR7_1: R7.1 R10.2 | length 119
  Bottom Layer w20: R10.2@4007.2,813.88 4090,731.08 R7.1@4090,729.21
NetR8_1: R8.1 U2.6 | length 94.2
  Bottom Layer w25: R8.1@3262.2,933.48 3282.79,912.89 U2.6@3282.79,847.78
NetR9_1: R9.1 U2.5 | length 101.2
  Bottom Layer w25: R9.1@3207.99,933.48 3207.99,916.01 3245.39,878.61 U2.5@3245.39,847.78
NetR11_1: R11.1 R13.1 | length 71.8
  Bottom Layer w50: R11.1@1052.09,745.18 R13.1@1123.91,745.18
NetR12_1: R12.1 U3.5 | length 64.6
  Bottom Layer w10: 3393,636.51 U3.5@3417.13,636.51
  Bottom Layer w20: R12.1@3353.16,638.12 3354.77,636.51 3393,636.51
NetR13_2: R13.2 R16.2 | length 69.6
  Bottom Layer w50: R13.2@1238.09,745.18 R16.2@1307.71,745.18
NetR18_2: R18.2 U3.9 | length 79.1
  Bottom Layer w10: U3.9@3476.18,803.83 3476.18,832.25 3485.82,841.89 3492.89,841.89 3510.17,859.17 R18.2@3515.75,859.17
NetR21_2: R21.2 U3.8 | length 69.2
  Bottom Layer w10: U3.8@3456.5,803.83 R21.2@3457.28,871.89 ; R21.2@3456.5,862.89 R21.2@3457.28,863.68
NetR30_2: R30.2 U6.1 | length 67.7
  Bottom Layer w20: U6.1@2850.98,641.28 2850.98,577.35 R30.2@2853.62,574.71
NetR31_1: R31.1 U5.4 | length 75.1
  Top Layer w20: R31.1@1380.29,2812.82 1383.79,2809.32 U5.4@1383.79,2739.16
NetR32_2: R32.2 U4.4 | length 504
  Top Layer w20: R32.2@1256.61,2365.18 v1(1310.12,2365.18) ; U4.4@1347.48,1993.05 v1(1391.97,1993.05)
  Bottom Layer w20: v1(1310.12,2365.18) 1310.12,2329.88 1356,2284 1356,2029.02 v1(1391.97,1993.05)
NetR36_2: R36.2 R37.1 U4.3 | length 122.3
  Top Layer w20: U4.3@1347.48,1884.78 1347.48,1835.02 R36.2@1358.46,1824.03 R37.1@1415.47,1824.03
NetR43_1: R43.1 R49.1 | length 555.8
  Signal Layer 2 w20: v1(1498.46,850) 1498.46,519.78 1508.62,509.62 R49.1@1508.62,355.18
  Bottom Layer w20: R43.1@1497.4,906.32 1498.46,905.26 v1(1498.46,850)
NetR44_2: R44.2 R45.1 | length 58
  Bottom Layer w30: R44.2@1552.4,848.34 R45.1@1552.4,906.32
NetR48_1: R48.1 R52.2 | length 58
  Bottom Layer w30: R52.2@1607.4,848.34 R48.1@1607.4,906.32
NetR55_1: R55.1 R55.2 R56.1 | length 927.3
  Signal Layer 2 w20: v1(2790,936.84) 2819.84,936.84 2837,919.68 2837,862.77 2824,849.77 2824,689.1 2788,653.1 2788,519.44 2899.44,408 2942.29,408 R55.2@2995.12,355.18 R55.1@3093.54,355.18
  Bottom Layer w15: R56.1@2722.4,909.07 2750.17,936.84 v1(2790,936.84)
NetR57_1: R57.1 U8.4 | length 67.6
  Bottom Layer w15: R57.1@2667.4,909.07 2667.4,874.83 2680.94,861.28 U8.4@2680.94,847.1
NetR58_2: R58.2 U7.5 | length 88.1
  Bottom Layer w20: R58.2@2372.14,970.84 2372.26,970.72 U7.5@2372.26,882.82
VIN: C2.2 C3.1 C4.1 C100.2 J1.1 R7.2 T1.1 TP2.1 | length 5062.6
  Signal Layer 2 w20: J1.1@318,934 180,796 180,490 240,430 415,430 756,89 1111,89 3758,87 4006,335 4006,534.03 4085.12,613.15 4163.11,613.15 v1(4165,615.04)
  Bottom Layer w20: R7.2@4090,615.04 v1(4165,615.04)
VOUT: C9.1 C10.1 C12.2 C101.2 D1.1 J2.1 R11.2 TP4.1 | length 6820.8
  Signal Layer 3 w20: v1(935,671) 935,506.25 858.75,430 120,430 98.6,451.4 98.6,2960.26 798.34,3660 2340,3660 TP4.1@2605,3395
  Bottom Layer w20: v1(935,671) 935,742.26 R11.2@937.91,745.18
  Bottom Layer w25: J2.1@2345,3325 2415,3395 TP4.1@2605,3395
pads on no net: H3.1 H4.1 H5.1 H6.1 H7.0 H8.0 H9.0 H10.0 U8.1 U9.1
